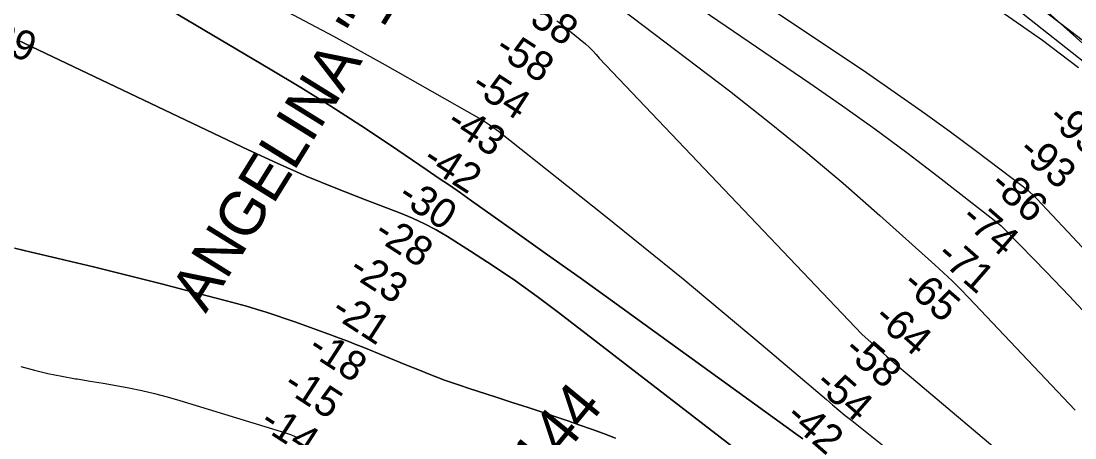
# Model space of a CAD drawing. Extents: x 3477039 to 3515015, y 546746 to 572297.
# Drawn here: x 3497998 to 3500384, y 563045 to 563990 of the extents above; entities that cross this region are included whole.
import ezdxf

# ---------------------------------------------------------------- set-up
doc = ezdxf.new("R2010")
doc.units = 0
for name, color, linetype in [('V-CHAN-NAID', 7, 'Continuous'), ('V-RIVR-IDEN', 7, 'Continuous'), ('V-RIVR-RANG', 7, 'Continuous'), ('V-RRAP-RVMT', 7, 'Continuous'), ('V-TOPO-DPTH', 7, 'Continuous'), ('V-TOPO-MAJR', 7, 'Continuous'), ('V-TOPO-MINR', 7, 'Continuous')]:
    doc.layers.add(name, color=color, linetype=linetype)

msp = doc.modelspace()

# ---------------------------------------------------------------- linework, layer by layer
at = {"layer": 'V-RRAP-RVMT'}
msp.add_lwpolyline([(3500309.2, 564022.1), (3500402.1, 563939.2)], dxfattribs=at)
msp.add_lwpolyline([(3500309.2, 564022.1), (3500402.1, 563939.2)], dxfattribs=at)
at = {"layer": 'V-TOPO-DPTH'}
for points in [[(3497892.6, 564214.1), (3498028.2, 564182.7), (3498049.8, 564176.6), (3498070.9, 564169.2), (3498091.3, 564159.9), (3498111.1, 564149.3), (3498562.5, 563881.2), (3498631.4, 563839.4), (3498699.8, 563796.9), (3498767.4, 563753.1), (3498834.5, 563708.5), (3498917.6, 563652.2), (3498942.7, 563635), (3498967.8, 563617.8), (3498992.7, 563600.4), (3499017.6, 563582.9), (3499116, 563513.2), (3499189.9, 563460.6), (3499263.7, 563407.9), (3499337.3, 563355), (3499410.9, 563301.9), (3499752.4, 563054.5), (3499767.9, 563043.4)], [(3499767.9, 563043.4), (3499752.4, 563054.5), (3499410.9, 563301.9), (3499337.3, 563355), (3499263.7, 563407.9), (3499189.9, 563460.6), (3499116, 563513.2), (3499017.6, 563582.9), (3498992.7, 563600.4), (3498967.8, 563617.8), (3498942.7, 563635), (3498917.6, 563652.2), (3498834.5, 563708.5), (3498767.4, 563753.1), (3498699.8, 563796.9), (3498631.4, 563839.4), (3498562.5, 563881.2), (3498111.1, 564149.3), (3498091.3, 564159.9), (3498070.9, 564169.2), (3498049.8, 564176.6), (3498028.2, 564182.7), (3497892.6, 564214.1)], [(3497990.8, 563947), (3498512.4, 563698.3), (3498577.9, 563668), (3498643.9, 563638.8), (3498710.6, 563611.2), (3498777.8, 563584.7), (3498856.9, 563554.6), (3498884.5, 563543.2), (3498911.5, 563530.7), (3498937.7, 563516.7), (3498963.4, 563501.6), (3499015.9, 563468.7), (3499066.9, 563435.6), (3499117.3, 563401.6), (3499166.6, 563366.1), (3499215.2, 563329.6), (3499670, 562978.2)], [(3499670, 562978.2), (3499215.2, 563329.6), (3499166.6, 563366.1), (3499117.3, 563401.6), (3499066.9, 563435.6), (3499015.9, 563468.7), (3498963.4, 563501.6), (3498937.7, 563516.7), (3498911.5, 563530.7), (3498884.5, 563543.2), (3498856.9, 563554.6), (3498777.8, 563584.7), (3498710.6, 563611.2), (3498643.9, 563638.8), (3498577.9, 563668), (3498512.4, 563698.3), (3497990.8, 563947)], [(3499343.6, 563045.1), (3499316.8, 563055.2), (3499289.9, 563065.1), (3499262.9, 563074.6), (3499235.8, 563084), (3499218.2, 563089.9), (3499182.2, 563102), (3499146.2, 563114), (3499110.2, 563125.8), (3499074.1, 563137.5), (3499010.7, 563157.8), (3498992.8, 563163.8), (3498974.9, 563170), (3498957.1, 563176.5), (3498939.5, 563183.2), (3498921.9, 563190.1), (3498904.3, 563197.1), (3498886.7, 563204.2), (3498869.2, 563211.3), (3498774.4, 563250.1), (3498756.1, 563257.4), (3498737.7, 563264.6), (3498719.3, 563271.6), (3498700.8, 563278.4), (3498620, 563307.7), (3498597.9, 563315.5), (3498575.6, 563323), (3498553.2, 563330.2), (3498530.7, 563337), (3498508.2, 563343.6), (3498485.6, 563350.1), (3498462.9, 563356.3), (3498440.2, 563362.3), (3498367.5, 563381.3), (3498316.3, 563394.6), (3498265.1, 563407.6), (3498213.8, 563420.3), (3498162.4, 563432.7), (3498097.9, 563448.2), (3498078.8, 563452.8), (3498059.6, 563457.4), (3498040.5, 563461.9), (3498021.4, 563466.5), (3498002.2, 563471), (3497983.1, 563475.6)], [(3499343.6, 563045.1), (3499316.8, 563055.2), (3499289.9, 563065.1), (3499262.9, 563074.6), (3499235.8, 563084), (3499218.2, 563089.9), (3499182.2, 563102), (3499146.2, 563114), (3499110.2, 563125.8), (3499074.1, 563137.5), (3499010.7, 563157.8), (3498992.8, 563163.8), (3498974.9, 563170), (3498957.1, 563176.5), (3498939.5, 563183.2), (3498921.9, 563190.1), (3498904.3, 563197.1), (3498886.7, 563204.2), (3498869.2, 563211.3), (3498774.4, 563250.1), (3498756.1, 563257.4), (3498737.7, 563264.6), (3498719.3, 563271.6), (3498700.8, 563278.4), (3498620, 563307.7), (3498597.9, 563315.5), (3498575.6, 563323), (3498553.2, 563330.2), (3498530.7, 563337), (3498508.2, 563343.6), (3498485.6, 563350.1), (3498462.9, 563356.3), (3498440.2, 563362.3), (3498367.5, 563381.3), (3498316.3, 563394.6), (3498265.1, 563407.6), (3498213.8, 563420.3), (3498162.4, 563432.7), (3498097.9, 563448.2), (3498078.8, 563452.8), (3498059.6, 563457.4), (3498040.5, 563461.9), (3498021.4, 563466.5), (3498002.2, 563471), (3497983.1, 563475.6)]]:
    msp.add_lwpolyline(points, dxfattribs=at)
at = {"layer": 'V-TOPO-MAJR'}
msp.add_lwpolyline([(3498586.7, 564018.8), (3498705.2, 563955.9), (3498822.6, 563891), (3499035.4, 563769.9), (3499046.7, 563763.1), (3499057.8, 563755.9), (3499068.6, 563748.3), (3499079.1, 563740.3), (3499317.4, 563550.8), (3499407.4, 563478.6), (3499496.9, 563405.7), (3499585.6, 563332), (3499673.9, 563257.6), (3499821.3, 563132.2), (3499835.5, 563120.2), (3499849.8, 563108.3), (3499864.2, 563096.5), (3499878.7, 563084.8), (3499962.1, 563018.2)], dxfattribs=at)
at = {"layer": 'V-TOPO-MINR'}
for points in [[(3500458.3, 563902.2), (3499648.6, 564523.7), (3499638.4, 564531.2), (3499628.2, 564538.6), (3499617.7, 564545.6), (3499607.1, 564552.4), (3499596.3, 564558.9), (3499585.3, 564565.1), (3499574.2, 564571), (3499562.9, 564576.7), (3498978.8, 564856.8), (3498888.8, 564899), (3498798.3, 564940.1), (3498707.1, 564979.6), (3498615.5, 565018.1), (3498462.7, 565080.6), (3498447, 565086.7), (3498431.2, 565092.6), (3498415.2, 565097.9), (3498399.1, 565103), (3497397.6, 565366.9)], [(3500463.7, 563850.1), (3500209.7, 564051.4), (3499995.8, 564212.9), (3499885.9, 564289.6), (3499774.5, 564364.3), (3499571.5, 564496.3), (3499560.5, 564503.3), (3499549.4, 564510), (3499538.1, 564516.5), (3499526.6, 564522.8), (3499364.3, 564609.6), (3499271.4, 564658.5), (3499178.1, 564706.8), (3499084.3, 564754.1), (3498990.1, 564800.6), (3498438.2, 565069.4), (3498431.4, 565072.5), (3498424.5, 565075.4), (3497290.4, 565311.9)], [(3500392.5, 563884), (3500351.7, 563915.3), (3500310.5, 563946.1), (3500268.6, 563975.8), (3500226.2, 564004.9), (3499970.2, 564175.9), (3499917.1, 564210.4), (3499863.7, 564244.3), (3499810, 564277.7), (3499795.4, 564286.7), (3499748.7, 564315.2), (3499701.8, 564343.4), (3499654.7, 564371.3), (3499607.4, 564398.9), (3499563.3, 564424.5), (3499537.9, 564439), (3499512.4, 564453.3), (3499486.8, 564467.4), (3499461, 564481.2), (3498925.8, 564763.9), (3498839.3, 564807.5), (3498751.8, 564848.7)], [(3497892.6, 564214.1), (3498028.2, 564182.7), (3498049.8, 564176.6), (3498070.9, 564169.2), (3498091.3, 564159.9), (3498111.1, 564149.3), (3498562.5, 563881.2), (3498631.4, 563839.4), (3498699.8, 563796.9), (3498767.4, 563753.1), (3498834.5, 563708.5), (3498917.6, 563652.2), (3498942.7, 563635), (3498967.8, 563617.8), (3498992.7, 563600.4), (3499017.6, 563582.9), (3499116, 563513.2), (3499189.9, 563460.6), (3499263.7, 563407.9), (3499337.3, 563355), (3499410.9, 563301.9), (3499752.4, 563054.5), (3499767.9, 563043.4)], [(3499415, 564206.6), (3499912.1, 563873.1), (3499975.2, 563829.9), (3500037.8, 563786), (3500099.7, 563741), (3500161, 563695.3), (3500266.6, 563615.1), (3500274.6, 563608.8), (3500282.3, 563602.2), (3500289.7, 563595.2), (3500296.8, 563588), (3500368.3, 563512.6), (3500410.6, 563467.1)], [(3499334.2, 564157), (3499784.3, 563849.6), (3499858.1, 563798.2), (3499931.2, 563745.9), (3500003.2, 563692.2), (3500074.6, 563637.6), (3500201, 563539), (3500208.6, 563532.8), (3500216, 563526.5), (3500223.1, 563519.8), (3500230.1, 563513), (3500320, 563421.1), (3500371.1, 563367.6), (3500421.4, 563313.3)], [(3499284.7, 564073.6), (3499601.8, 563831.6), (3499688.8, 563763.4), (3499774.8, 563694), (3499859.1, 563622.5), (3499942.3, 563549.7), (3500067.2, 563437.9), (3500086.9, 563419.7), (3500106.3, 563401.3), (3500125.3, 563382.4), (3500143.9, 563363.1), (3500384.4, 563108.4)], [(3499210.9, 563990.8), (3499213.4, 563989.1), (3499215.8, 563987.2), (3499276.2, 563938.1), (3499284.7, 563930.7), (3499292.7, 563922.9), (3499300.1, 563914.4), (3499307.1, 563905.6), (3499901.5, 563280.5), (3499929.3, 563255.6), (3499957.2, 563230.9), (3499985.4, 563206.5), (3500013.8, 563182.3), (3500246.5, 562986)], [(3497990.8, 563947), (3498512.4, 563698.3), (3498577.9, 563668), (3498643.9, 563638.8), (3498710.6, 563611.2), (3498777.8, 563584.7), (3498856.9, 563554.6), (3498884.5, 563543.2), (3498911.5, 563530.7), (3498937.7, 563516.7), (3498963.4, 563501.6), (3499015.9, 563468.7), (3499066.9, 563435.6), (3499117.3, 563401.6), (3499166.6, 563366.1), (3499215.2, 563329.6), (3499670, 562978.2)], [(3497983.1, 563475.6), (3498002.2, 563471), (3498021.4, 563466.5), (3498040.5, 563461.9), (3498059.6, 563457.4), (3498078.8, 563452.8), (3498097.9, 563448.2), (3498162.4, 563432.7), (3498213.8, 563420.3), (3498265.1, 563407.6), (3498316.3, 563394.6), (3498367.5, 563381.3), (3498440.2, 563362.3), (3498462.9, 563356.3), (3498485.6, 563350.1), (3498508.2, 563343.6), (3498530.7, 563337), (3498553.2, 563330.2), (3498575.6, 563323), (3498597.9, 563315.5), (3498620, 563307.7), (3498700.8, 563278.4), (3498719.3, 563271.6), (3498737.7, 563264.6), (3498756.1, 563257.4), (3498774.4, 563250.1), (3498869.2, 563211.3), (3498886.7, 563204.2), (3498904.3, 563197.1), (3498921.9, 563190.1), (3498939.5, 563183.2), (3498957.1, 563176.5), (3498974.9, 563170), (3498992.8, 563163.8), (3499010.7, 563157.8), (3499074.1, 563137.5), (3499110.2, 563125.8), (3499146.2, 563114), (3499182.2, 563102), (3499218.2, 563089.9), (3499235.8, 563084), (3499262.9, 563074.6), (3499289.9, 563065.1), (3499316.8, 563055.2), (3499343.6, 563045.1)], [(3497997.7, 563207.3), (3498028.3, 563199), (3498059.1, 563191.5), (3498090.2, 563185.2), (3498121.4, 563179.6), (3498125.5, 563179), (3498154.8, 563174.3), (3498184.1, 563169.3), (3498213.2, 563164.1), (3498242.4, 563158.6), (3498271.4, 563152.6), (3498300.3, 563145.9), (3498328.9, 563138.3), (3498357.4, 563130.1), (3498587.3, 563059.6), (3498594.2, 563057.4), (3498601.2, 563055.2), (3498608, 563052.8), (3498614.9, 563050.3), (3498623.6, 563047), (3498626.1, 563046.1), (3498628.6, 563045.2)]]:
    msp.add_lwpolyline(points, dxfattribs=at)

# ---------------------------------------------------------------- texts
at = {"layer": 'V-CHAN-NAID'}
msp.add_text('ANGELINA "146" (144.3)', height=100, rotation=58.1906, dxfattribs=at).set_placement((3498416.1, 563325.9))
at = {"layer": 'V-RIVR-IDEN'}
msp.add_text('144', height=100, rotation=50.5257, dxfattribs=at).set_placement((3499177.4, 562944))
at = {"layer": 'V-RIVR-RANG'}
for s, rotation, p in [('-58', 327.0465, (3499121.6, 564001.9)), ('-29', 338.8323, (3497895.3, 563942.1)), ('-58', 327.0465, (3499067, 563918.1)), ('-54', 327.0465, (3499013.1, 563833.9)), ('-43', 327.0465, (3498957.4, 563750.9)), ('-95', 318.9356, (3500318.9, 563765.2)), ('-93', 318.9356, (3500251.8, 563691)), ('-42', 327.0465, (3498903.2, 563666.8)), ('-86', 318.9356, (3500187.6, 563614.4)), ('-30', 327.0465, (3498847, 563584)), ('-74', 318.9356, (3500122.3, 563538.6)), ('-28', 327.0465, (3498793.1, 563499.8)), ('-71', 318.9356, (3500066.7, 563454.4)), ('-23', 327.0465, (3498736.3, 563417.5)), ('-65', 318.9356, (3499989.5, 563389)), ('-21', 327.0465, (3498696.1, 563324.4)), ('-64', 318.9356, (3499925, 563312.6)), ('-18', 327.0465, (3498643.5, 563239.3)), ('-58', 318.9356, (3499857, 563239.3)), ('-15', 327.0465, (3498588, 563156.1)), ('-54', 318.9356, (3499791.7, 563163.5)), ('-14', 327.0465, (3498534.9, 563071.3)), ('-42', 318.9356, (3499725.2, 563088.8))]:
    msp.add_text(s, height=67, rotation=rotation, dxfattribs=at).set_placement(p)

doc.saveas('drawing.dxf')
